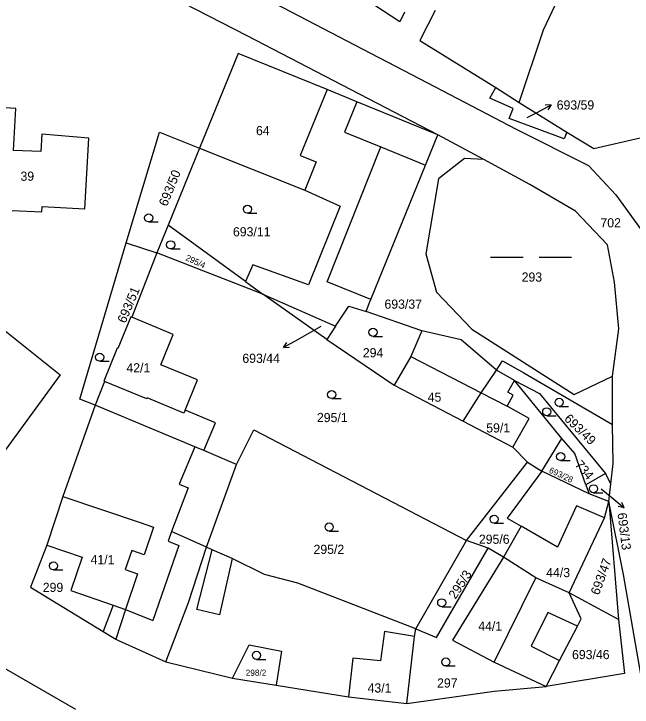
# Model space of a CAD drawing. Extents: x -747333 to -743907, y -1134120 to -1130051.
# Drawn here: x -746360.5 to -746246, y -1132212.3 to -1132083.8 of the extents above; entities that cross this region are included whole.
import ezdxf

# ---------------------------------------------------------------- set-up
doc = ezdxf.new("R2010")
doc.units = 0
for name, color, linetype in [('Hranice parcel', 7, 'Continuous'), ('Parcelní čísla', 7, 'Continuous'), ('Pop  PČ popisy', 7, 'Continuous'), ('Vnitřní kresba', 7, 'Continuous'), ('Značky kultur', 7, 'Continuous')]:
    doc.layers.add(name, color=color, linetype=linetype)

msp = doc.modelspace()

# ---------------------------------------------------------------- linework, layer by layer
at = {"layer": 'Hranice parcel'}
for p, q in [((-746271.22, -1132097.41), (-746266.88, -1132100.2)), ((-746266.88, -1132100.2), (-746258.07, -1132105.71)), ((-746273.47, -1132110.79), (-746281.98, -1132106.18)), ((-746326.13, -1132108.66), (-746331.96, -1132122.97)), ((-746326.13, -1132108.66), (-746306.63, -1132116.44)), ((-746331.96, -1132122.97), (-746334.03, -1132128.06)), ((-746317.6, -1132133.4), (-746331.96, -1132122.97)), ((-746339.72, -1132126.2), (-746334.03, -1132128.06)), ((-746334.03, -1132128.06), (-746338.7, -1132140.02)), ((-746314.39, -1132135.73), (-746334.03, -1132128.06)), ((-746317.6, -1132133.4), (-746314.39, -1132135.73)), ((-746314.39, -1132135.73), (-746300.91, -1132141.67)), ((-746302.53, -1132144.17), (-746314.39, -1132135.73)), ((-746338.7, -1132140.02), (-746338.87, -1132139.95)), ((-746331.03, -1132143.2), (-746338.7, -1132140.02)), ((-746284.93, -1132142.52), (-746295.24, -1132138.98)), ((-746300.91, -1132141.67), (-746302.53, -1132144.17)), ((-746302.53, -1132144.17), (-746290.06, -1132152.64)), ((-746271.08, -1132149.84), (-746269.98, -1132148.07)), ((-746267.76, -1132151.76), (-746271.08, -1132149.84)), ((-746249.58, -1132159.89), (-746249.63, -1132150.94)), ((-746290.06, -1132152.64), (-746277.28, -1132159.31)), ((-746259.02, -1132162.52), (-746267.76, -1132151.76)), ((-746327.01, -1132164.06), (-746345.51, -1132156.33)), ((-746249.5, -1132167.15), (-746249.58, -1132159.89)), ((-746262.67, -1132168.54), (-746259.02, -1132162.52)), ((-746325.35, -1132164.75), (-746327.01, -1132164.06)), ((-746319.28, -1132167.34), (-746325.35, -1132164.75)), ((-746276.66, -1132181.4), (-746265.37, -1132166.88)), ((-746265.37, -1132166.88), (-746262.67, -1132168.54)), ((-746324.85, -1132182.62), (-746319.28, -1132167.34)), ((-746249.91, -1132170.92), (-746249.5, -1132167.15)), ((-746262.67, -1132168.54), (-746269.15, -1132177.26)), ((-746253.91, -1132172.73), (-746262.67, -1132168.54)), ((-746250.91, -1132168.99), (-746254.52, -1132171.09)), ((-746249.91, -1132170.92), (-746250.91, -1132168.99)), ((-746254.52, -1132171.09), (-746253.91, -1132172.73)), ((-746250.26, -1132174.19), (-746249.91, -1132170.92)), ((-746250.26, -1132174.19), (-746253.91, -1132172.73)), ((-746251.07, -1132177.2), (-746250.26, -1132174.19)), ((-746250.26, -1132174.19), (-746248.47, -1132196.06)), ((-746257.62, -1132191.11), (-746251.07, -1132177.2)), ((-746286.03, -1132197.8), (-746276.66, -1132181.4)), ((-746272.66, -1132182.81), (-746276.66, -1132181.4)), ((-746269.83, -1132184.49), (-746272.66, -1132182.81)), ((-746248.47, -1132196.06), (-746257.62, -1132191.11)), ((-746385.31, -1132191.74), (-746349.14, -1132212.69)), ((-746342.14, -1132193.39), (-746344.02, -1132198.28)), ((-746341.17, -1132199.97), (-746332.36, -1132203.87)), ((-746332.36, -1132203.87), (-746320.04, -1132206.95)), ((-746320.04, -1132206.95), (-746311.91, -1132208.23))]:
    msp.add_line(p, q, dxfattribs=at)
for points in [[(-746266.88, -1132100.2), (-746262.42, -1132086.72), (-746242.88, -1132045.31)], [(-746281.98, -1132106.18), (-746317.29, -1132087.85), (-746364.32, -1132063.67)], [(-746324.12, -1132075.54), (-746282.49, -1132097.32), (-746267.43, -1132105.17), (-746254.03, -1132111.91), (-746248.97, -1132117.3)], [(-746288.15, -1132083.49), (-746289.02, -1132085.27), (-746300.43, -1132077.73)], [(-746282.45, -1132083.18), (-746285.29, -1132088.71), (-746271.22, -1132097.41)], [(-746258.07, -1132105.71), (-746253.04, -1132108.76), (-746235.88, -1132104.76), (-746228.31, -1132088.24)], [(-746281.98, -1132106.18), (-746296.99, -1132100.07), (-746302.49, -1132097.83), (-746318.98, -1132091.11), (-746326.13, -1132108.66)], [(-746258.07, -1132105.71), (-746258.56, -1132106.96), (-746268.77, -1132103.18), (-746268.04, -1132101.35), (-746272.31, -1132099.42), (-746271.22, -1132097.41)], [(-746355.36, -1132120.45), (-746355.33, -1132119.49), (-746347.42, -1132119.91), (-746346.68, -1132106.82), (-746355.36, -1132106.11), (-746355.58, -1132109.28), (-746360.59, -1132109.08), (-746360.16, -1132101.31), (-746366.14, -1132100.93)], [(-746339.72, -1132126.2), (-746333.57, -1132105.7), (-746326.13, -1132108.66)], [(-746295.24, -1132138.98), (-746294.66, -1132137.31), (-746294.42, -1132136.7), (-746284.28, -1132111.82), (-746281.98, -1132106.18)], [(-746273.47, -1132110.79), (-746277.01, -1132110.58), (-746281.86, -1132114.35), (-746284.17, -1132128.28), (-746282.24, -1132135.36), (-746275.7, -1132142.21), (-746256.69, -1132154.37), (-746249.63, -1132150.94)], [(-746249.63, -1132150.94), (-746248.4, -1132142.18), (-746249.24, -1132133.5), (-746250.55, -1132126.59), (-746256.46, -1132120.37), (-746264.93, -1132115.42), (-746273.47, -1132110.79)], [(-746306.63, -1132116.44), (-746300.07, -1132119.44), (-746305.92, -1132134.02), (-746316.23, -1132130.3), (-746317.6, -1132133.4)], [(-746248.97, -1132117.3), (-746244.31, -1132123.79), (-746241.88, -1132132.35), (-746241.11, -1132138.34), (-746243.12, -1132156.17), (-746244.31, -1132165.56), (-746243.27, -1132178.27), (-746239.96, -1132195.24)], [(-746360.86, -1132120.23), (-746355.36, -1132120.45)], [(-746345.51, -1132156.33), (-746348.32, -1132155.23), (-746339.72, -1132126.2)], [(-746376.13, -1132131.39), (-746351.94, -1132150.67), (-746363.92, -1132166.96), (-746374.04, -1132177.52)], [(-746300.91, -1132141.67), (-746298.49, -1132137.94), (-746295.24, -1132138.98)], [(-746338.87, -1132139.95), (-746341.27, -1132145.79), (-746341.4, -1132145.74), (-746343.89, -1132151.87), (-746343.74, -1132151.93), (-746345.51, -1132156.33)], [(-746284.93, -1132142.52), (-746286.99, -1132147.28), (-746290.06, -1132152.64)], [(-746271.08, -1132149.84), (-746277.62, -1132144.21), (-746284.93, -1132142.52)], [(-746326.54, -1132151.64), (-746333.32, -1132148.85), (-746331.03, -1132143.2)], [(-746269.98, -1132148.07), (-746266.05, -1132150.32), (-746249.58, -1132159.89)], [(-746277.28, -1132159.31), (-746273.97, -1132154.01), (-746271.08, -1132149.84)], [(-746325.35, -1132164.75), (-746323.2, -1132159.6), (-746328.82, -1132157.26), (-746326.54, -1132151.64)], [(-746267.76, -1132151.76), (-746263.14, -1132154.13), (-746250.91, -1132168.99)], [(-746345.51, -1132156.33), (-746351.46, -1132173.24), (-746354.43, -1132182.28)], [(-746277.28, -1132159.31), (-746268.1, -1132164.11), (-746265.37, -1132166.88)], [(-746319.28, -1132167.34), (-746316.09, -1132160.88), (-746276.66, -1132181.4)], [(-746254.52, -1132171.09), (-746256.61, -1132165.3), (-746259.02, -1132162.52)], [(-746239.72, -1132225.13), (-746242.13, -1132218.98), (-746247.56, -1132187.7), (-746250.26, -1132174.19)], [(-746269.15, -1132177.26), (-746266.52, -1132178.78), (-746269.83, -1132184.49)], [(-746354.43, -1132182.28), (-746357.46, -1132190.03), (-746344.02, -1132198.28)], [(-746354.43, -1132182.28), (-746347.89, -1132184.52), (-746349.97, -1132190.7), (-746342.14, -1132193.39)], [(-746332.36, -1132203.87), (-746328.16, -1132192.93), (-746324.85, -1132182.62)], [(-746286.03, -1132197.8), (-746307.91, -1132189.33), (-746314.12, -1132187.7), (-746320.12, -1132184.74), (-746323.77, -1132183.11), (-746324.85, -1132182.62)], [(-746286.03, -1132197.8), (-746282.24, -1132199.36), (-746272.66, -1132182.81)], [(-746269.83, -1132184.49), (-746279.28, -1132199.88), (-746271.52, -1132203.95), (-746261.88, -1132208.46)], [(-746257.62, -1132191.11), (-746263.83, -1132188.34), (-746269.83, -1132184.49)], [(-746261.88, -1132208.46), (-746259.4, -1132203.66), (-746256.11, -1132197.3), (-746255.38, -1132195.9), (-746257.62, -1132191.11)], [(-746248.47, -1132196.06), (-746247.35, -1132206.07), (-746261.88, -1132208.46)], [(-746287.72, -1132211.62), (-746286.31, -1132199.21), (-746286.03, -1132197.8)], [(-746344.02, -1132198.28), (-746341.62, -1132199.71), (-746341.17, -1132199.97)], [(-746320.04, -1132206.95), (-746316.94, -1132200.77), (-746310.94, -1132201.9), (-746311.91, -1132208.23)], [(-746311.91, -1132208.23), (-746298.54, -1132210.41), (-746287.72, -1132211.62)], [(-746287.72, -1132211.62), (-746271.53, -1132209.32), (-746261.88, -1132208.46)]]:
    msp.add_lwpolyline(points, dxfattribs=at)
at = {"layer": 'Pop  PČ popisy'}
for p, q in [((-746263.59, -1132102.07), (-746260.94, -1132100.661)), ((-746260.94, -1132100.661), (-746262.06, -1132100.689)), ((-746260.94, -1132100.661), (-746261.589, -1132101.573)), ((-746265.39, -1132103.02), (-746263.59, -1132102.07)), ((-746303.64, -1132141.76), (-746307.97, -1132144.18)), ((-746307.97, -1132144.18), (-746310.595, -1132145.635)), ((-746310.595, -1132145.635), (-746309.962, -1132144.711)), ((-746310.595, -1132145.635), (-746309.476, -1132145.587)), ((-746251.69, -1132171.81), (-746249.74, -1132173.44)), ((-746249.74, -1132173.44), (-746247.441, -1132175.369)), ((-746247.441, -1132175.369), (-746247.886, -1132174.342)), ((-746247.441, -1132175.369), (-746248.53, -1132175.109))]:
    msp.add_line(p, q, dxfattribs=at)
at = {"layer": 'Vnitřní kresba'}
for p, q in [((-746302.49, -1132097.83), (-746307.46, -1132110.02)), ((-746296.99, -1132100.07), (-746299.29, -1132105.7)), ((-746299.29, -1132105.7), (-746292.53, -1132108.46)), ((-746302.51, -1132133.44), (-746292.53, -1132108.46)), ((-746292.53, -1132108.46), (-746284.28, -1132111.82)), ((-746307.46, -1132110.02), (-746304.5, -1132111.22)), ((-746304.5, -1132111.22), (-746306.63, -1132116.44)), ((-746294.42, -1132136.7), (-746302.51, -1132133.44)), ((-746286.99, -1132147.28), (-746273.97, -1132154.01)), ((-746335.91, -1132155.17), (-746343.74, -1132151.93)), ((-746269.01, -1132153.93), (-746267.76, -1132151.76)), ((-746273.97, -1132154.01), (-746269.1, -1132156.5)), ((-746267.99, -1132154.49), (-746269.01, -1132153.93)), ((-746335.83, -1132154.99), (-746335.91, -1132155.17)), ((-746329.03, -1132157.78), (-746335.83, -1132154.99)), ((-746269.1, -1132156.5), (-746267.99, -1132154.49)), ((-746265.06, -1132158.79), (-746269.1, -1132156.5)), ((-746328.82, -1132157.26), (-746329.03, -1132157.78)), ((-746268.1, -1132164.11), (-746265.06, -1132158.79)), ((-746327.01, -1132164.06), (-746329.9, -1132170.98)), ((-746328.24, -1132171.67), (-746331.34, -1132179.73)), ((-746329.9, -1132170.98), (-746328.24, -1132171.67)), ((-746351.46, -1132173.24), (-746337.16, -1132178.1)), ((-746256.3, -1132174.95), (-746259.81, -1132182.62)), ((-746251.07, -1132177.2), (-746256.3, -1132174.95)), ((-746337.16, -1132178.1), (-746334.67, -1132178.95)), ((-746334.67, -1132178.95), (-746336.41, -1132184.06)), ((-746331.34, -1132179.73), (-746331.97, -1132181.56)), ((-746324.85, -1132182.62), (-746331.34, -1132179.73)), ((-746259.81, -1132182.62), (-746266.52, -1132178.78)), ((-746330, -1132182.34), (-746334.82, -1132196.26)), ((-746331.97, -1132181.56), (-746330, -1132182.34)), ((-746338.7, -1132183.28), (-746339.9, -1132186.81)), ((-746336.41, -1132184.06), (-746338.7, -1132183.28)), ((-746326.61, -1132194.2), (-746323.77, -1132183.11)), ((-746320.12, -1132184.74), (-746322.45, -1132195.19)), ((-746339.9, -1132186.81), (-746337.61, -1132187.59)), ((-746337.61, -1132187.59), (-746339.85, -1132194.17)), ((-746271.52, -1132203.95), (-746263.83, -1132188.34)), ((-746342.14, -1132193.39), (-746339.85, -1132194.17)), ((-746339.85, -1132194.17), (-746341.62, -1132199.71)), ((-746339.85, -1132194.17), (-746334.82, -1132196.26)), ((-746322.45, -1132195.19), (-746326.61, -1132194.2)), ((-746261.59, -1132194.74), (-746264.68, -1132201.02)), ((-746256.11, -1132197.3), (-746261.59, -1132194.74)), ((-746291.88, -1132198.29), (-746292.59, -1132203.73)), ((-746286.31, -1132199.21), (-746291.88, -1132198.29)), ((-746264.68, -1132201.02), (-746259.4, -1132203.66)), ((-746297.74, -1132203.24), (-746298.54, -1132210.41)), ((-746292.59, -1132203.73), (-746297.74, -1132203.24))]:
    msp.add_line(p, q, dxfattribs=at)
at = {"layer": 'Značky kultur'}
for p, q in [((-746317.243, -1132120.74), (-746315.493, -1132120.74)), ((-746335.573, -1132122.35), (-746333.823, -1132122.35)), ((-746331.483, -1132127.35), (-746329.733, -1132127.35)), ((-746272.189, -1132128.9), (-746266.189, -1132128.9)), ((-746263.189, -1132128.9), (-746257.189, -1132128.9)), ((-746293.983, -1132143.56), (-746292.233, -1132143.56)), ((-746344.643, -1132148.18), (-746342.893, -1132148.18)), ((-746301.643, -1132155.11), (-746299.893, -1132155.11)), ((-746259.493, -1132156.54), (-746257.743, -1132156.54)), ((-746261.793, -1132158.29), (-746260.043, -1132158.29)), ((-746259.213, -1132166.6), (-746257.463, -1132166.6)), ((-746253.123, -1132172.56), (-746251.373, -1132172.56)), ((-746271.543, -1132178.21), (-746269.793, -1132178.21)), ((-746302.113, -1132179.66), (-746300.363, -1132179.66)), ((-746353.213, -1132186.86), (-746351.463, -1132186.86)), ((-746281.253, -1132193.7), (-746279.503, -1132193.7)), ((-746315.593, -1132203.45), (-746313.843, -1132203.45)), ((-746280.483, -1132204.67), (-746278.733, -1132204.67))]:
    msp.add_line(p, q, dxfattribs=at)
for centre in [(-746317.243, -1132119.99), (-746335.573, -1132121.6), (-746331.483, -1132126.6), (-746293.983, -1132142.81), (-746344.643, -1132147.43), (-746301.643, -1132154.36), (-746259.493, -1132155.79), (-746261.793, -1132157.54), (-746259.213, -1132165.85), (-746253.123, -1132171.81), (-746271.543, -1132177.46), (-746302.113, -1132178.91), (-746353.213, -1132186.11), (-746281.253, -1132192.95), (-746315.593, -1132202.7), (-746280.483, -1132203.92)]:
    msp.add_circle(centre, 0.75, dxfattribs=at)

# ---------------------------------------------------------------- texts
at = {"layer": 'Parcelní čísla'}
for s, height, p in [('693/59', 1.7, (-746259.94, -1132101.52)), ('64', 1.7, (-746315.67, -1132106.27)), ('39', 1.7, (-746359.32, -1132114.72)), ('702', 1.7, (-746251.84, -1132123.36)), ('693/11', 1.7, (-746319.94, -1132125.03)), ('293', 1.7, (-746266.44, -1132133.42)), ('693/37', 1.7, (-746291.86, -1132138.44)), ('294', 1.7, (-746295.87, -1132147.45)), ('693/44', 1.7, (-746318.201, -1132148.483)), ('42/1', 1.7, (-746339.69, -1132150.25)), ('45', 1.7, (-746283.85, -1132155.68)), ('295/1', 1.7, (-746304.38, -1132159.46)), ('59/1', 1.7, (-746273, -1132161.38)), ('295/6', 1.7, (-746274.363, -1132182.02)), ('295/2', 1.7, (-746305.01, -1132183.9)), ('41/1', 1.7, (-746346.33, -1132185.8)), ('44/3', 1.7, (-746261.89, -1132188.2)), ('299', 1.7, (-746355.19, -1132190.95)), ('44/1', 1.7, (-746274.48, -1132198.13)), ('693/46', 1.7, (-746257.1, -1132203.4)), ('298/2', 1.14, (-746317.57, -1132206.49)), ('43/1', 1.7, (-746294.99, -1132209.59)), ('297', 1.7, (-746282.11, -1132208.67))]:
    msp.add_text(s, height=height, dxfattribs=at).set_placement(p)
for s, height, rotation, p in [('693/50', 1.7, 68, (-746332.18, -1132119.593)), ('295/4', 1.14, 335, (-746328.826, -1132129.4)), ('693/51', 1.7, 67, (-746339.879, -1132141.255)), ('693/49', 1.7, 316, (-746258.68, -1132159.001)), ('734', 1.7, 310, (-746256.67, -1132167.413)), ('693/28', 1.14, 335, (-746261.48, -1132168.776)), ('693/13', 1.7, 277, (-746248.682, -1132176.355)), ('693/47', 1.7, 70, (-746252.121, -1132191.65)), ('295/3', 1.7, 57, (-746278.697, -1132192.392))]:
    msp.add_text(s, height=height, rotation=rotation, dxfattribs=at).set_placement(p)

doc.saveas('drawing.dxf')
